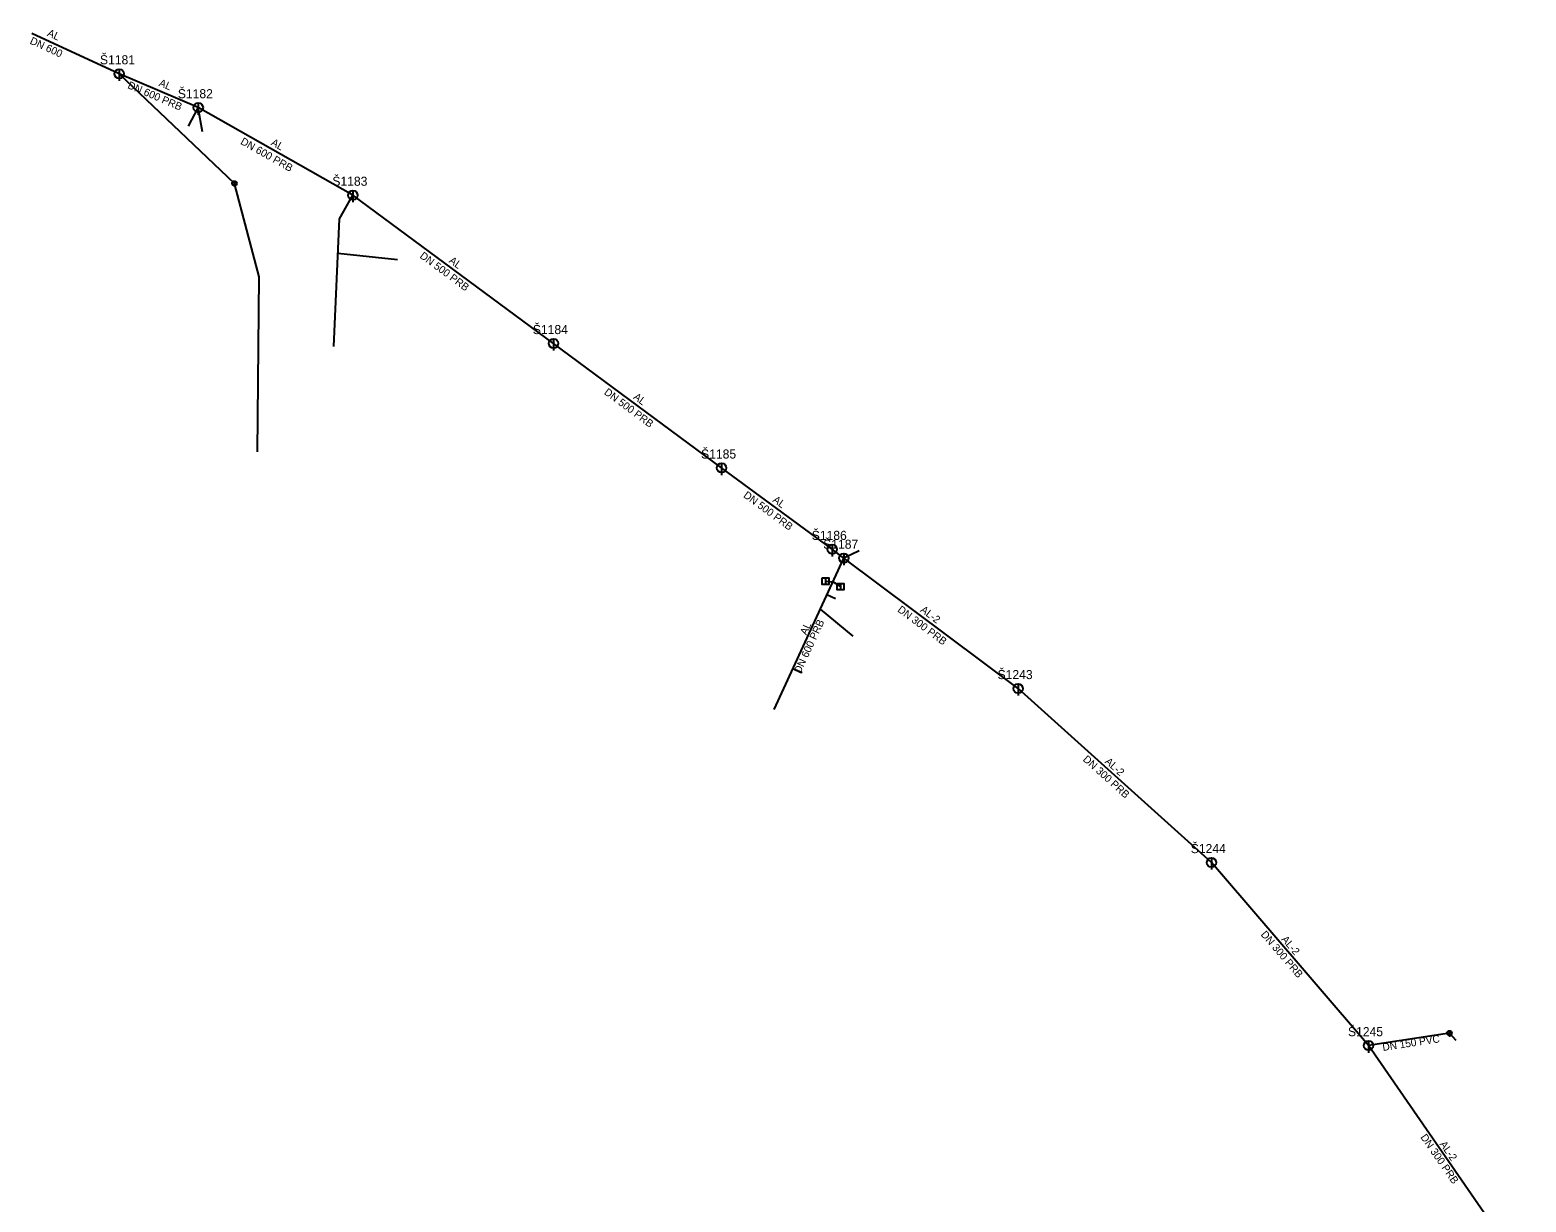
# Model space of a CAD drawing. Extents: x -482852 to -482359, y -1127974 to -1127429.
# Drawn here: x -482851.8 to -482533.9, y -1127677.8 to -1127428.7 of the extents above; entities that cross this region are included whole.
import ezdxf

# ---------------------------------------------------------------- set-up
doc = ezdxf.new("R2010")
doc.units = 0
for name, color, linetype in [('_pripojka_kanal_destova_priblizne_', 7, 'Continuous'), ('_pripojka_kanal_jednotna_priblizne_', 7, 'Continuous'), ('_stoka_jednotna_smvak_prevzato_z_dokumentace_', 7, 'Continuous'), ('Default', 7, 'Continuous'), ('MoLevel 119', 7, 'Continuous'), ('MoLevel 120', 7, 'Continuous'), ('MoLevel 124', 7, 'Continuous'), ('MoLevel 57', 7, 'Continuous'), ('MoLevel 63', 7, 'Continuous'), ('MoLevel 68', 7, 'Continuous'), ('MoLevel 69', 7, 'Continuous')]:
    doc.layers.add(name, color=color, linetype=linetype)

# ---------------------------------------------------------------- blocks, each defined once
blk = doc.blocks.new('_vpust_')
at = {"layer": 'Default'}
blk.add_line((0, 0.000025), (0, -0.000025), dxfattribs=at)
blk.add_lwpolyline([(-0.000035, 0.000035), (0.000035, 0.000035), (0.000035, -0.000035), (-0.000035, -0.000035), (-0.000035, 0.000035)], dxfattribs=at)
blk = doc.blocks.new('_sachta_kanal_prip_')
at = {"layer": 'Default'}
blk.add_line((0, 0.00005), (0, -0.000075), dxfattribs=at)
blk.add_circle((0, 0), 0.00005, dxfattribs=at)
blk = doc.blocks.new('_sachta_kanal_prevzato_z_dokumentace_')
at = {"layer": 'Default'}
blk.add_line((0, 0.00005), (0, -0.000075), dxfattribs=at)
blk.add_circle((0, 0), 0.00005, dxfattribs=at)

msp = doc.modelspace()

# ---------------------------------------------------------------- linework, layer by layer
at = {"layer": '_pripojka_kanal_destova_priblizne_'}
for p, q in [((-482773.71, -1127477.52), (-482786.38, -1127476.2)), ((-482682.78, -1127545.83), (-482681.22, -1127545.98)), ((-482679.61, -1127547), (-482681.22, -1127545.98))]:
    msp.add_line(p, q, dxfattribs=at)
msp.add_lwpolyline([(-482787.29, -1127495.94), (-482786.04, -1127468.85), (-482783.21, -1127463.81)], dxfattribs=at)
at = {"layer": '_pripojka_kanal_jednotna_priblizne_'}
for p, q in [((-482808.38, -1127461.3), (-482832.87, -1127438)), ((-482818.17, -1127449.12), (-482816.05, -1127445.22)), ((-482815.16, -1127450.33), (-482816.05, -1127445.22)), ((-482675.61, -1127539.41), (-482678.91, -1127540.95)), ((-482680.69, -1127549.61), (-482682.49, -1127548.74)), ((-482676.92, -1127557.5), (-482683.88, -1127551.76)), ((-482687.75, -1127565.3), (-482689.72, -1127564.48)), ((-482550.21, -1127641.89), (-482567.4, -1127644.54)), ((-482548.75, -1127643.44), (-482550.21, -1127641.89))]:
    msp.add_line(p, q, dxfattribs=at)
msp.add_lwpolyline([(-482803.48, -1127518.32), (-482803.13, -1127481.15), (-482808.38, -1127461.3)], dxfattribs=at)
at = {"layer": '_stoka_jednotna_smvak_prevzato_z_dokumentace_'}
for p, q in [((-482832.87, -1127438), (-482851.41, -1127429.47)), ((-482783.21, -1127463.81), (-482816.05, -1127445.21)), ((-482740.57, -1127495.33), (-482783.21, -1127463.81)), ((-482704.86, -1127521.78), (-482740.57, -1127495.33)), ((-482681.35, -1127539.07), (-482704.86, -1127521.78)), ((-482693.68, -1127573.1), (-482678.91, -1127540.95)), ((-482678.91, -1127540.95), (-482681.35, -1127539.07)), ((-482641.86, -1127568.65), (-482678.91, -1127540.95)), ((-482600.77, -1127605.63), (-482641.86, -1127568.65)), ((-482567.4, -1127644.54), (-482600.77, -1127605.63)), ((-482533.92, -1127692.93), (-482567.4, -1127644.54))]:
    msp.add_line(p, q, dxfattribs=at)
msp.add_lwpolyline([(-482816.05, -1127445.21), (-482832.87, -1127438), (-482832.87, -1127438)], dxfattribs=at)

# ---------------------------------------------------------------- block references
at = {"layer": 'MoLevel 119', "xscale": 20000, "yscale": 20000}
for p in [(-482832.87, -1127438), (-482816.05, -1127445.21), (-482783.21, -1127463.81), (-482740.57, -1127495.33), (-482704.86, -1127521.78), (-482681.35, -1127539.07), (-482678.91, -1127540.95), (-482641.86, -1127568.65), (-482600.77, -1127605.63), (-482567.4, -1127644.54)]:
    msp.add_blockref('_sachta_kanal_prevzato_z_dokumentace_', p, dxfattribs=at)
at = {"layer": 'MoLevel 57', "xscale": 10000, "yscale": 10000}
for p in [(-482808.38, -1127461.3), (-482550.21, -1127641.89)]:
    msp.add_blockref('_sachta_kanal_prip_', p, dxfattribs=at)
at = {"layer": 'MoLevel 63', "xscale": 20000, "yscale": 20000}
for p in [(-482682.78, -1127545.83), (-482679.61, -1127547)]:
    msp.add_blockref('_vpust_', p, dxfattribs=at)

# ---------------------------------------------------------------- texts
at = {"layer": 'MoLevel 120'}
for s, p in [('Š1181', (-482836.95, -1127436)), ('Š1182', (-482820.41, -1127443.21)), ('Š1183', (-482787.57, -1127461.81)), ('Š1184', (-482744.97, -1127493.33)), ('Š1185', (-482709.22, -1127519.78)), ('Š1186', (-482685.71, -1127537.07)), ('Š1187', (-482683.27, -1127538.95)), ('Š1243', (-482646.22, -1127566.65)), ('Š1244', (-482605.17, -1127603.63)), ('Š1245', (-482571.76, -1127642.54))]:
    msp.add_text(s, height=1.926, dxfattribs=at).set_placement(p)
at = {"layer": 'MoLevel 124'}
msp.add_text('DN 150 PVC', height=1.605, rotation=8.7655, dxfattribs=at).set_placement((-482564.31, -1127645.69))
at = {"layer": 'MoLevel 68'}
for s, rotation, p in [('DN 600', 335.2901, (-482851.99, -1127431.56)), ('DN 600 PRB', 336.7787, (-482831.22, -1127441.02)), ('DN 600 PRB', 330.4831, (-482807.24, -1127452.85)), ('DN 500 PRB', 323.5277, (-482769.14, -1127477)), ('DN 500 PRB', 323.4731, (-482729.97, -1127505.98)), ('DN 500 PRB', 323.6681, (-482700.37, -1127527.88)), ('DN 300 PRB', 323.2168, (-482667.62, -1127552.19)), ('DN 600 PRB', 65.3255, (-482688.11, -1127565.61)), ('DN 300 PRB', 318.0136, (-482628.21, -1127583.89)), ('DN 300 PRB', 310.6171, (-482590.4, -1127620.98)), ('DN 300 PRB', 304.6785, (-482556.44, -1127664.01))]:
    msp.add_text(s, height=1.605, rotation=rotation, dxfattribs=at).set_placement(p)
at = {"layer": 'MoLevel 69'}
for s, rotation, p in [('AL', 335.2901, (-482848.3, -1127429.89)), ('AL', 336.7787, (-482824.58, -1127440.52)), ('AL', 330.4831, (-482800.76, -1127453.07)), ('AL', 323.5277, (-482762.93, -1127478)), ('AL', 323.4731, (-482723.76, -1127506.98)), ('AL', 323.6681, (-482694.15, -1127528.86)), ('AL-2', 323.2168, (-482662.77, -1127552.22)), ('AL', 65.3255, (-482686.84, -1127557.41)), ('AL-2', 318.0136, (-482623.53, -1127584.35)), ('AL-2', 310.6171, (-482586.03, -1127622.02)), ('AL-2', 304.6785, (-482552.36, -1127665.48))]:
    msp.add_text(s, height=1.605, rotation=rotation, dxfattribs=at).set_placement(p)

doc.saveas('drawing.dxf')
